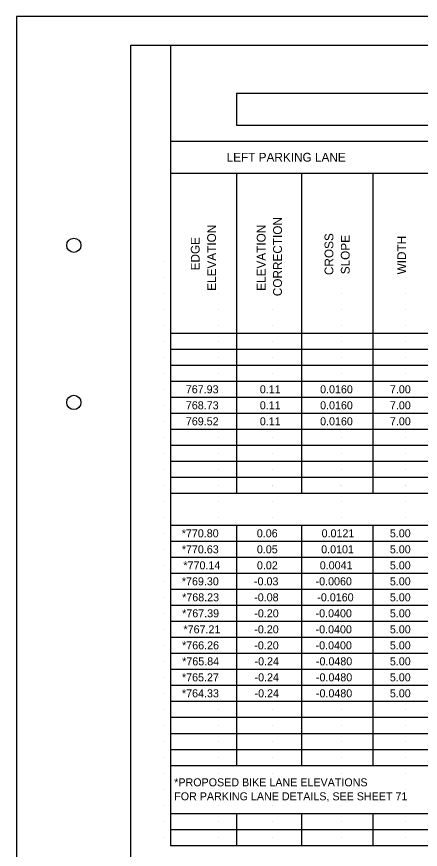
# Model space of a CAD drawing. Extents: x -15.4 to 18.6, y -12.6 to 9.4.
# Drawn here: x -15.36 to -8.3, y -5.18 to 9.39 of the extents above; entities that cross this region are included whole.
import ezdxf

# ---------------------------------------------------------------- set-up
doc = ezdxf.new("R2010")
doc.units = 0
for name, color, linetype in [('SH_Border', 7, 'Continuous'), ('SH_Cut_Line', 7, 'Continuous'), ('SH_Data', 7, 'Continuous'), ('SH_Text', 7, 'Continuous')]:
    doc.layers.add(name, color=color, linetype=linetype)

msp = doc.modelspace()

# ---------------------------------------------------------------- linework, layer by layer
at = {"layer": 'SH_Border'}
msp.add_lwpolyline([(-13.357, 8.888), (18.143, 8.888), (18.143, -12.112), (-13.357, -12.112)], close=True, dxfattribs=at)
for centre in [(-14.357, 5.388), (-14.357, 2.638)]:
    msp.add_circle(centre, 0.125, dxfattribs=at)
at = {"layer": 'SH_Cut_Line'}
msp.add_lwpolyline([(-15.357, -12.612), (18.643, -12.612), (18.643, 9.388), (-15.357, 9.388)], close=True, dxfattribs=at)
at = {"layer": 'SH_Data'}
for p, q in [((-12.667, 8.888), (15.877, 8.888)), ((-12.667, 8.888), (-12.667, -5.112)), ((-11.514, 8.048), (13.999, 8.048)), ((-11.514, 8.048), (-11.514, 7.488)), ((-11.514, 7.488), (13.999, 7.488)), ((-12.667, 7.208), (15.877, 7.208)), ((-12.667, 6.648), (14.576, 6.648)), ((-11.514, 6.648), (-11.514, 1.048)), ((-10.377, 6.648), (-10.377, 1.048)), ((-9.126, 6.648), (-9.126, 1.048)), ((-12.782, 5.108), (-12.782, 5.108)), ((-11.832, 5.108), (-11.832, 5.108)), ((-10.882, 5.108), (-10.882, 5.108)), ((-9.682, 5.108), (-9.682, 5.108)), ((-8.557, 5.108), (-8.557, 5.108)), ((-12.782, 4.828), (-12.782, 4.828)), ((-11.832, 4.828), (-11.832, 4.828)), ((-10.882, 4.828), (-10.882, 4.828)), ((-9.682, 4.828), (-9.682, 4.828)), ((-8.557, 4.828), (-8.557, 4.828)), ((-12.782, 4.548), (-12.782, 4.548)), ((-11.832, 4.548), (-11.832, 4.548)), ((-10.882, 4.548), (-10.882, 4.548)), ((-9.682, 4.548), (-9.682, 4.548)), ((-8.557, 4.548), (-8.557, 4.548)), ((-12.782, 4.268), (-12.782, 4.268)), ((-11.832, 4.268), (-11.832, 4.268)), ((-10.882, 4.268), (-10.882, 4.268)), ((-9.682, 4.268), (-9.682, 4.268)), ((-8.557, 4.268), (-8.557, 4.268)), ((-12.782, 3.988), (-12.782, 3.988)), ((-11.832, 3.988), (-11.832, 3.988)), ((-10.882, 3.988), (-10.882, 3.988)), ((-9.682, 3.988), (-9.682, 3.988)), ((-8.557, 3.988), (-8.557, 3.988)), ((-12.667, 3.848), (15.877, 3.848)), ((-12.782, 3.708), (-12.782, 3.708)), ((-11.832, 3.708), (-11.832, 3.708)), ((-10.882, 3.708), (-10.882, 3.708)), ((-9.682, 3.708), (-9.682, 3.708)), ((-8.557, 3.708), (-8.557, 3.708)), ((-12.667, 3.568), (15.877, 3.568)), ((-12.782, 3.428), (-12.782, 3.428)), ((-11.832, 3.428), (-11.832, 3.428)), ((-10.882, 3.428), (-10.882, 3.428)), ((-9.682, 3.428), (-9.682, 3.428)), ((-8.557, 3.428), (-8.557, 3.428)), ((-12.667, 3.288), (15.877, 3.288)), ((-12.782, 3.148), (-12.782, 3.148)), ((-11.832, 3.148), (-11.832, 3.148)), ((-10.882, 3.148), (-10.882, 3.148)), ((-9.682, 3.148), (-9.682, 3.148)), ((-8.557, 3.148), (-8.557, 3.148)), ((-12.667, 3.008), (15.877, 3.008)), ((-12.782, 2.868), (-12.782, 2.868)), ((-11.832, 2.868), (-11.832, 2.868)), ((-10.882, 2.868), (-10.882, 2.868)), ((-9.682, 2.868), (-9.682, 2.868)), ((-8.557, 2.868), (-8.557, 2.868)), ((-12.667, 2.728), (15.877, 2.728)), ((-12.782, 2.588), (-12.782, 2.588)), ((-11.832, 2.588), (-11.832, 2.588)), ((-10.882, 2.588), (-10.882, 2.588)), ((-9.682, 2.588), (-9.682, 2.588)), ((-8.557, 2.588), (-8.557, 2.588)), ((-12.667, 2.448), (15.877, 2.448)), ((-12.782, 2.308), (-12.782, 2.308)), ((-11.832, 2.308), (-11.832, 2.308)), ((-10.882, 2.308), (-10.882, 2.308)), ((-9.682, 2.308), (-9.682, 2.308)), ((-8.557, 2.308), (-8.557, 2.308)), ((-12.667, 2.168), (15.877, 2.168)), ((-12.782, 2.028), (-12.782, 2.028)), ((-11.832, 2.028), (-11.832, 2.028)), ((-10.882, 2.028), (-10.882, 2.028)), ((-9.682, 2.028), (-9.682, 2.028)), ((-8.557, 2.028), (-8.557, 2.028)), ((-12.667, 1.888), (15.877, 1.888)), ((-12.782, 1.748), (-12.782, 1.748)), ((-12.782, 1.748), (-12.782, 1.748)), ((-12.667, 1.608), (15.877, 1.608)), ((-11.832, 1.748), (-11.832, 1.748)), ((-11.832, 1.748), (-11.832, 1.748)), ((-10.882, 1.748), (-10.882, 1.748)), ((-10.882, 1.748), (-10.882, 1.748)), ((-9.682, 1.748), (-9.682, 1.748)), ((-9.682, 1.748), (-9.682, 1.748)), ((-8.557, 1.748), (-8.557, 1.748)), ((-8.557, 1.748), (-8.557, 1.748)), ((-12.782, 1.468), (-12.782, 1.468)), ((-12.782, 1.468), (-12.782, 1.468)), ((-11.832, 1.468), (-11.832, 1.468)), ((-11.832, 1.468), (-11.832, 1.468)), ((-10.882, 1.468), (-10.882, 1.468)), ((-10.882, 1.468), (-10.882, 1.468)), ((-9.682, 1.468), (-9.682, 1.468)), ((-9.682, 1.468), (-9.682, 1.468)), ((-8.557, 1.468), (-8.557, 1.468)), ((-8.557, 1.468), (-8.557, 1.468)), ((-12.667, 1.328), (15.877, 1.328)), ((-12.785, 1.188), (-12.785, 1.188)), ((-12.785, 1.188), (-12.785, 1.188)), ((-12.782, 1.188), (-12.782, 1.188)), ((-11.835, 1.188), (-11.835, 1.188)), ((-11.835, 1.188), (-11.835, 1.188)), ((-11.832, 1.188), (-11.832, 1.188)), ((-10.885, 1.188), (-10.885, 1.188)), ((-10.885, 1.188), (-10.885, 1.188)), ((-10.882, 1.188), (-10.882, 1.188)), ((-9.685, 1.188), (-9.685, 1.188)), ((-9.685, 1.188), (-9.685, 1.188)), ((-9.682, 1.188), (-9.682, 1.188)), ((-8.56, 1.188), (-8.56, 1.188)), ((-8.56, 1.188), (-8.56, 1.188)), ((-8.557, 1.188), (-8.557, 1.188)), ((-12.667, 1.048), (15.877, 1.048)), ((-12.782, 0.908), (-12.782, 0.908)), ((-11.832, 0.908), (-11.832, 0.908)), ((-10.882, 0.908), (-10.882, 0.908)), ((-9.682, 0.908), (-9.682, 0.908)), ((-8.557, 0.908), (-8.557, 0.908)), ((-12.782, 0.628), (-12.782, 0.628)), ((-11.832, 0.628), (-11.832, 0.628)), ((-10.882, 0.628), (-10.882, 0.628)), ((-9.682, 0.628), (-9.682, 0.628)), ((-8.557, 0.628), (-8.557, 0.628)), ((-12.667, 0.488), (15.877, 0.488)), ((-11.514, 0.488), (-11.514, -3.712)), ((-10.377, 0.488), (-10.377, -3.712)), ((-9.126, 0.488), (-9.126, -3.712)), ((-12.782, 0.348), (-12.782, 0.348)), ((-11.832, 0.348), (-11.832, 0.348)), ((-10.882, 0.348), (-10.882, 0.348)), ((-9.682, 0.348), (-9.682, 0.348)), ((-8.557, 0.348), (-8.557, 0.348)), ((-12.667, 0.208), (15.877, 0.208)), ((-12.782, 0.068), (-12.782, 0.068)), ((-11.832, 0.068), (-11.832, 0.068)), ((-10.882, 0.068), (-10.882, 0.068)), ((-9.682, 0.068), (-9.682, 0.068)), ((-8.557, 0.068), (-8.557, 0.068)), ((-12.667, -0.072), (15.877, -0.072)), ((-12.782, -0.212), (-12.782, -0.212)), ((-11.832, -0.212), (-11.832, -0.212)), ((-10.882, -0.212), (-10.882, -0.212)), ((-9.682, -0.212), (-9.682, -0.212)), ((-8.557, -0.212), (-8.557, -0.212)), ((-12.667, -0.352), (15.877, -0.352)), ((-12.782, -0.492), (-12.782, -0.492)), ((-11.832, -0.492), (-11.832, -0.492)), ((-10.882, -0.492), (-10.882, -0.492)), ((-9.682, -0.492), (-9.682, -0.492)), ((-8.557, -0.492), (-8.557, -0.492)), ((-12.667, -0.632), (15.877, -0.632)), ((-12.782, -0.772), (-12.782, -0.772)), ((-11.832, -0.772), (-11.832, -0.772)), ((-10.882, -0.772), (-10.882, -0.772)), ((-9.682, -0.772), (-9.682, -0.772)), ((-8.557, -0.772), (-8.557, -0.772)), ((-12.667, -0.912), (15.877, -0.912)), ((-12.782, -1.052), (-12.782, -1.052)), ((-11.832, -1.052), (-11.832, -1.052)), ((-10.882, -1.052), (-10.882, -1.052)), ((-9.682, -1.052), (-9.682, -1.052)), ((-8.557, -1.052), (-8.557, -1.052)), ((-12.667, -1.192), (15.877, -1.192)), ((-12.782, -1.332), (-12.782, -1.332)), ((-11.832, -1.332), (-11.832, -1.332)), ((-10.882, -1.332), (-10.882, -1.332)), ((-9.682, -1.332), (-9.682, -1.332)), ((-8.557, -1.332), (-8.557, -1.332)), ((-12.667, -1.472), (15.877, -1.472)), ((-12.782, -1.612), (-12.782, -1.612)), ((-11.832, -1.612), (-11.832, -1.612)), ((-10.882, -1.612), (-10.882, -1.612)), ((-9.682, -1.612), (-9.682, -1.612)), ((-8.557, -1.612), (-8.557, -1.612)), ((-12.782, -1.892), (-12.782, -1.892)), ((-12.667, -1.752), (15.877, -1.752)), ((-11.832, -1.892), (-11.832, -1.892)), ((-10.882, -1.892), (-10.882, -1.892)), ((-9.682, -1.892), (-9.682, -1.892)), ((-8.557, -1.892), (-8.557, -1.892)), ((-12.667, -2.032), (15.877, -2.032)), ((-12.782, -2.172), (-12.782, -2.172)), ((-11.832, -2.172), (-11.832, -2.172)), ((-10.882, -2.172), (-10.882, -2.172)), ((-9.682, -2.172), (-9.682, -2.172)), ((-8.557, -2.172), (-8.557, -2.172)), ((-12.667, -2.312), (15.877, -2.312)), ((-12.782, -2.452), (-12.782, -2.452)), ((-11.832, -2.452), (-11.832, -2.452)), ((-10.882, -2.452), (-10.882, -2.452)), ((-9.682, -2.452), (-9.682, -2.452)), ((-8.557, -2.452), (-8.557, -2.452)), ((-12.667, -2.592), (15.877, -2.592)), ((-12.782, -2.732), (-12.782, -2.732)), ((-11.832, -2.732), (-11.832, -2.732)), ((-10.882, -2.732), (-10.882, -2.732)), ((-9.682, -2.732), (-9.682, -2.732)), ((-8.557, -2.732), (-8.557, -2.732)), ((-12.667, -2.872), (15.877, -2.872)), ((-12.782, -3.012), (-12.782, -3.012)), ((-11.832, -3.012), (-11.832, -3.012)), ((-10.882, -3.012), (-10.882, -3.012)), ((-9.682, -3.012), (-9.682, -3.012)), ((-8.557, -3.012), (-8.557, -3.012)), ((-12.667, -3.152), (15.877, -3.152)), ((-12.782, -3.292), (-12.782, -3.292)), ((-11.832, -3.292), (-11.832, -3.292)), ((-10.882, -3.292), (-10.882, -3.292)), ((-9.682, -3.292), (-9.682, -3.292)), ((-8.557, -3.292), (-8.557, -3.292)), ((-12.667, -3.432), (15.877, -3.432)), ((-12.782, -3.572), (-12.782, -3.572)), ((-11.832, -3.572), (-11.832, -3.572)), ((-10.882, -3.572), (-10.882, -3.572)), ((-9.682, -3.572), (-9.682, -3.572)), ((-8.557, -3.572), (-8.557, -3.572)), ((-12.667, -3.712), (15.877, -3.712)), ((-12.782, -3.852), (-12.782, -3.852)), ((-11.832, -3.852), (-11.832, -3.852)), ((-10.882, -3.852), (-10.882, -3.852)), ((-9.682, -3.852), (-9.682, -3.852)), ((-8.557, -3.852), (-8.557, -3.852)), ((-12.782, -4.132), (-12.782, -4.132)), ((-11.832, -4.132), (-11.832, -4.132)), ((-10.882, -4.132), (-10.882, -4.132)), ((-9.682, -4.132), (-9.682, -4.132)), ((-8.557, -4.132), (-8.557, -4.132)), ((-12.782, -4.412), (-12.782, -4.412)), ((-11.832, -4.412), (-11.832, -4.412)), ((-10.882, -4.412), (-10.882, -4.412)), ((-9.682, -4.412), (-9.682, -4.412)), ((-8.557, -4.412), (-8.557, -4.412)), ((-12.667, -4.552), (15.877, -4.552)), ((-11.514, -4.552), (-11.514, -5.112)), ((-10.377, -4.552), (-10.377, -5.112)), ((-9.126, -4.552), (-9.126, -5.112)), ((-12.782, -4.692), (-12.782, -4.692)), ((-11.832, -4.692), (-11.832, -4.692)), ((-10.882, -4.692), (-10.882, -4.692)), ((-9.682, -4.692), (-9.682, -4.692)), ((-8.557, -4.692), (-8.557, -4.692)), ((-12.667, -4.832), (15.877, -4.832)), ((-12.782, -4.972), (-12.782, -4.972)), ((-11.832, -4.972), (-11.832, -4.972)), ((-10.882, -4.972), (-10.882, -4.972)), ((-9.682, -4.972), (-9.682, -4.972)), ((-8.557, -4.972), (-8.557, -4.972)), ((-12.667, -5.112), (15.877, -5.112))]:
    msp.add_line(p, q, dxfattribs=at)

# ---------------------------------------------------------------- texts
at = {"layer": 'SH_Text'}
for s, height, p in [('LEFT PARKING LANE', 0.154, (-11.684, 6.851)), ('767.93', 0.14, (-12.398, 2.798)), ('0.11', 0.14, (-11.103, 2.798)), ('0.0160', 0.14, (-10.049, 2.798)), ('7.00', 0.14, (-8.828, 2.798)), ('768.73', 0.14, (-12.397, 2.518)), ('0.11', 0.14, (-11.103, 2.518)), ('0.0160', 0.14, (-10.049, 2.518)), ('7.00', 0.14, (-8.828, 2.518)), ('769.52', 0.14, (-12.397, 2.238)), ('0.11', 0.14, (-11.103, 2.238)), ('0.0160', 0.14, (-10.049, 2.238)), ('7.00', 0.14, (-8.828, 2.238)), ('*770.80', 0.14, (-12.469, 0.278)), ('0.06', 0.14, (-11.156, 0.278)), ('0.0121', 0.14, (-10.023, 0.278)), ('5.00', 0.14, (-8.829, 0.278)), ('*770.63', 0.14, (-12.468, -0.002)), ('0.05', 0.14, (-11.155, -0.002)), ('0.0101', 0.14, (-10.03, -0.002)), ('5.00', 0.14, (-8.829, -0.002)), ('*770.14', 0.14, (-12.44, -0.282)), ('0.02', 0.14, (-11.154, -0.282)), ('0.0041', 0.14, (-10.055, -0.282)), ('5.00', 0.14, (-8.829, -0.282)), ('*769.30', 0.14, (-12.467, -0.562)), ('-0.03', 0.14, (-11.205, -0.562)), ('-0.0060', 0.14, (-10.128, -0.562)), ('5.00', 0.14, (-8.829, -0.562)), ('*768.23', 0.14, (-12.462, -0.842)), ('-0.08', 0.14, (-11.202, -0.842)), ('-0.0160', 0.14, (-10.098, -0.842)), ('5.00', 0.14, (-8.829, -0.842)), ('*767.39', 0.14, (-12.462, -1.122)), ('-0.20', 0.14, (-11.2, -1.122)), ('-0.0400', 0.14, (-10.128, -1.122)), ('5.00', 0.14, (-8.829, -1.122)), ('*767.21', 0.14, (-12.439, -1.402)), ('-0.20', 0.14, (-11.2, -1.402)), ('-0.0400', 0.14, (-10.128, -1.402)), ('5.00', 0.14, (-8.829, -1.402)), ('*766.26', 0.14, (-12.463, -1.682)), ('-0.20', 0.14, (-11.2, -1.682)), ('-0.0400', 0.14, (-10.128, -1.682)), ('5.00', 0.14, (-8.829, -1.682)), ('*765.84', 0.14, (-12.461, -1.962)), ('-0.24', 0.14, (-11.196, -1.962)), ('-0.0480', 0.14, (-10.122, -1.962)), ('5.00', 0.14, (-8.829, -1.962)), ('*765.27', 0.14, (-12.465, -2.242)), ('-0.24', 0.14, (-11.196, -2.242)), ('-0.0480', 0.14, (-10.122, -2.242)), ('5.00', 0.14, (-8.829, -2.242)), ('*764.33', 0.14, (-12.465, -2.522)), ('-0.24', 0.14, (-11.196, -2.522)), ('-0.0480', 0.14, (-10.122, -2.522)), ('5.00', 0.14, (-8.829, -2.522)), ('*PROPOSED BIKE LANE ELEVATIONS', 0.14, (-12.601, -4.079)), ('FOR PARKING LANE DETAILS, SEE SHEET 71', 0.14, (-12.601, -4.324))]:
    msp.add_text(s, height=height, dxfattribs=at).set_placement(p)
for s, p in [('CORRECTION', (-10.717, 4.497)), ('ELEVATION', (-11.87, 4.591)), ('ELEVATION', (-11.003, 4.591)), ('CROSS', (-9.817, 4.866)), ('SLOPE', (-9.532, 4.881)), ('EDGE', (-12.156, 4.948)), ('WIDTH', (-8.546, 4.878))]:
    msp.add_text(s, height=0.154, rotation=90, dxfattribs=at).set_placement(p)

doc.saveas('drawing.dxf')
